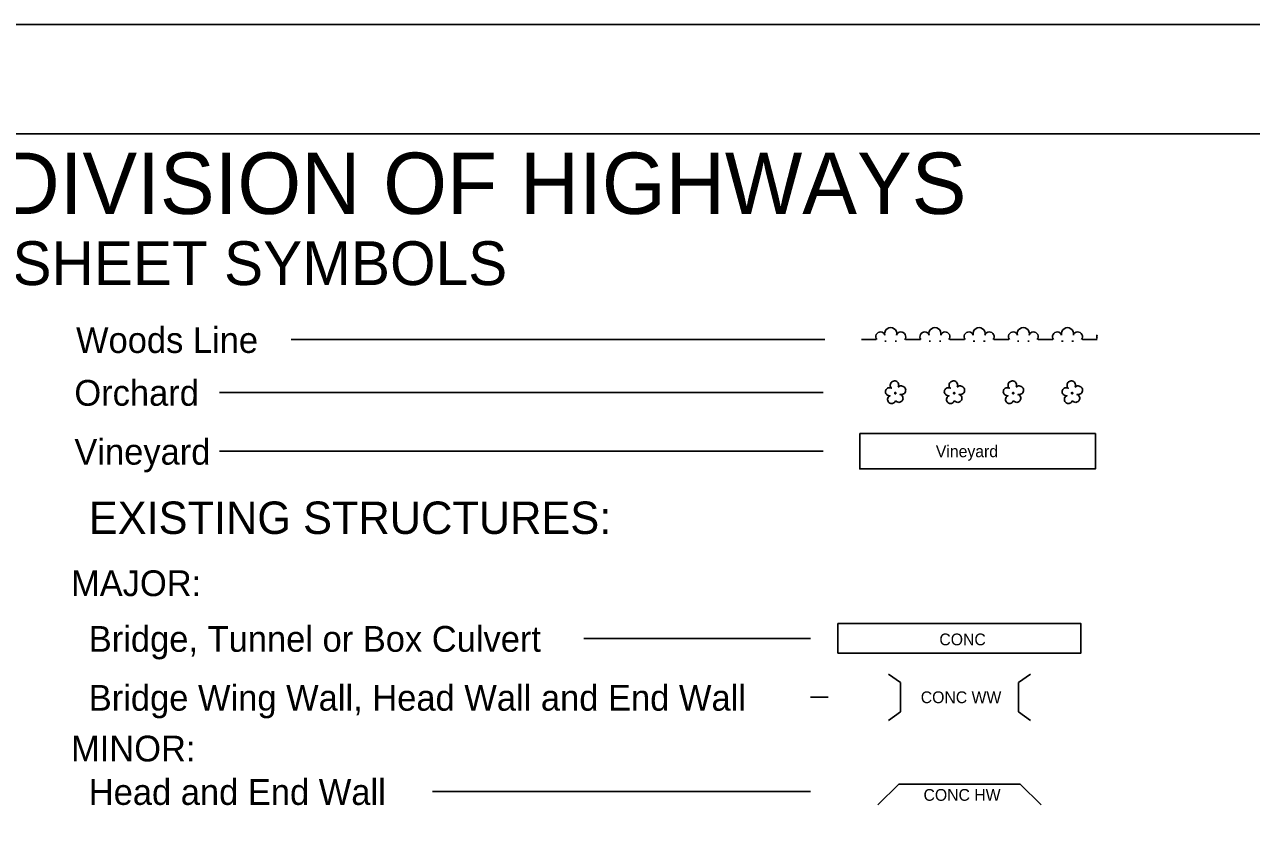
# Model space of a CAD drawing. Extents: x 1855058 to 1858918, y 1540202 to 1542502.
# Drawn here: x 1857984.5 to 1858404.6, y 1542229.1 to 1542501.8 of the extents above; entities that cross this region are included whole.
import ezdxf

# ---------------------------------------------------------------- set-up
doc = ezdxf.new("R2010")
doc.units = 0
for name, color, linetype in [('Default', 7, 'Continuous'), ('Exist Contamination Potential Cell', 7, 'Continuous'), ('Sheet Data Field CELL', 7, 'Continuous'), ('Sheet Symbology CELL', 7, 'Continuous')]:
    doc.layers.add(name, color=color, linetype=linetype)

msp = doc.modelspace()

# ---------------------------------------------------------------- linework, layer by layer
at = {"layer": 'Default'}
msp.add_lwpolyline([(1857118.6, 1542501.77), (1857118.6, 1541401.77), (1858818.6, 1541401.77), (1858818.6, 1542501.77)], close=True, dxfattribs=at)
at = {"layer": 'Exist Contamination Potential Cell'}
msp.add_line((1858818.6, 1542501.77), (1857118.6, 1542501.77), dxfattribs=at)
at = {"layer": 'Sheet Data Field CELL'}
for p, q in [((1858258.58, 1542393.83), (1858075.83, 1542393.83)), ((1858271.08, 1542393.83), (1858276.13, 1542393.83)), ((1858279.1, 1542393.33), (1858279.61, 1542393.33)), ((1858282.63, 1542393.33), (1858283.14, 1542393.33)), ((1858286.21, 1542393.83), (1858291.26, 1542393.83)), ((1858294.24, 1542393.33), (1858294.74, 1542393.33)), ((1858297.77, 1542393.33), (1858298.27, 1542393.33)), ((1858301.35, 1542393.83), (1858306.39, 1542393.83)), ((1858309.37, 1542393.33), (1858309.87, 1542393.33)), ((1858312.9, 1542393.33), (1858313.41, 1542393.33)), ((1858316.48, 1542393.83), (1858321.53, 1542393.83)), ((1858324.5, 1542393.33), (1858325.01, 1542393.33)), ((1858328.04, 1542393.33), (1858328.54, 1542393.33)), ((1858331.62, 1542393.83), (1858336.66, 1542393.83)), ((1858339.64, 1542393.33), (1858340.14, 1542393.33)), ((1858343.17, 1542393.33), (1858343.67, 1542393.33)), ((1858346.75, 1542393.83), (1858351.8, 1542393.83)), ((1858258.01, 1542375.74), (1858051.24, 1542375.74)), ((1858258.01, 1542355.56), (1858051.24, 1542355.56)), ((1858253.65, 1542291.49), (1858176, 1542291.49)), ((1858280.34, 1542279.24), (1858284.48, 1542276.36)), ((1858328.97, 1542279.24), (1858324.83, 1542276.36)), ((1858284.48, 1542276.36), (1858284.48, 1542266.27)), ((1858324.83, 1542276.36), (1858324.83, 1542266.27)), ((1858253.65, 1542271.31), (1858259.69, 1542271.31)), ((1858280.34, 1542263.38), (1858284.48, 1542266.27)), ((1858328.97, 1542263.38), (1858324.83, 1542266.27)), ((1858276.71, 1542234.42), (1858283.85, 1542241.55)), ((1858283.85, 1542241.55), (1858325.46, 1542241.55)), ((1858325.46, 1542241.55), (1858332.6, 1542234.42)), ((1858253.65, 1542239.03), (1858124.21, 1542239.03))]:
    msp.add_line(p, q, dxfattribs=at)
for points in [[(1858283.68, 1542377.51), (1858283.83, 1542377.81), (1858283.88, 1542378.11), (1858283.83, 1542378.42), (1858283.78, 1542378.72), (1858283.63, 1542378.97), (1858283.48, 1542379.22), (1858283.22, 1542379.43), (1858282.97, 1542379.58), (1858282.62, 1542379.68), (1858282.37, 1542379.68), (1858282.06, 1542379.63), (1858281.76, 1542379.53), (1858281.51, 1542379.38), (1858281.26, 1542379.17), (1858281.1, 1542378.87), (1858281, 1542378.62), (1858280.95, 1542378.32), (1858280.95, 1542378.01), (1858281, 1542377.71), (1858281.15, 1542377.46), (1858281.36, 1542377.16), (1858281.1, 1542377.31), (1858280.8, 1542377.36), (1858280.5, 1542377.36), (1858280.25, 1542377.26), (1858279.99, 1542377.16), (1858279.74, 1542376.95), (1858279.54, 1542376.75), (1858279.39, 1542376.5), (1858279.34, 1542376.25), (1858279.29, 1542375.89), (1858279.34, 1542375.64), (1858279.44, 1542375.39), (1858279.64, 1542375.14), (1858279.79, 1542374.94), (1858280.04, 1542374.78), (1858280.35, 1542374.63), (1858280.6, 1542374.58), (1858280.9, 1542374.58), (1858280.65, 1542374.48), (1858280.4, 1542374.28), (1858280.25, 1542374.08), (1858280.15, 1542373.78), (1858280.04, 1542373.47), (1858280.04, 1542373.22), (1858280.1, 1542372.92), (1858280.25, 1542372.67), (1858280.4, 1542372.41), (1858280.6, 1542372.21), (1858280.85, 1542372.06), (1858281.1, 1542371.96), (1858281.41, 1542371.96), (1858281.71, 1542371.96), (1858281.96, 1542372.01), (1858282.21, 1542372.21), (1858282.47, 1542372.36), (1858282.72, 1542372.82)], [(1858303.86, 1542377.51), (1858304.01, 1542377.81), (1858304.06, 1542378.11), (1858304.01, 1542378.42), (1858303.96, 1542378.72), (1858303.81, 1542378.97), (1858303.65, 1542379.22), (1858303.4, 1542379.43), (1858303.15, 1542379.58), (1858302.8, 1542379.68), (1858302.54, 1542379.68), (1858302.24, 1542379.63), (1858301.94, 1542379.53), (1858301.69, 1542379.38), (1858301.43, 1542379.17), (1858301.28, 1542378.87), (1858301.18, 1542378.62), (1858301.13, 1542378.32), (1858301.13, 1542378.01), (1858301.18, 1542377.71), (1858301.33, 1542377.46), (1858301.54, 1542377.16), (1858301.28, 1542377.31), (1858300.98, 1542377.36), (1858300.68, 1542377.36), (1858300.43, 1542377.26), (1858300.17, 1542377.16), (1858299.92, 1542376.95), (1858299.72, 1542376.75), (1858299.57, 1542376.5), (1858299.52, 1542376.25), (1858299.47, 1542375.89), (1858299.52, 1542375.64), (1858299.62, 1542375.39), (1858299.82, 1542375.14), (1858299.97, 1542374.94), (1858300.22, 1542374.78), (1858300.53, 1542374.63), (1858300.78, 1542374.58), (1858301.08, 1542374.58), (1858300.83, 1542374.48), (1858300.58, 1542374.28), (1858300.43, 1542374.08), (1858300.32, 1542373.78), (1858300.22, 1542373.47), (1858300.22, 1542373.22), (1858300.27, 1542372.92), (1858300.43, 1542372.67), (1858300.58, 1542372.41), (1858300.78, 1542372.21), (1858301.03, 1542372.06), (1858301.28, 1542371.96), (1858301.59, 1542371.96), (1858301.89, 1542371.96), (1858302.14, 1542372.01), (1858302.39, 1542372.21), (1858302.65, 1542372.36), (1858302.9, 1542372.82)], [(1858324.03, 1542377.51), (1858324.19, 1542377.81), (1858324.24, 1542378.11), (1858324.19, 1542378.42), (1858324.14, 1542378.72), (1858323.98, 1542378.97), (1858323.83, 1542379.22), (1858323.58, 1542379.43), (1858323.33, 1542379.58), (1858322.98, 1542379.68), (1858322.72, 1542379.68), (1858322.42, 1542379.63), (1858322.12, 1542379.53), (1858321.87, 1542379.38), (1858321.61, 1542379.17), (1858321.46, 1542378.87), (1858321.36, 1542378.62), (1858321.31, 1542378.32), (1858321.31, 1542378.01), (1858321.36, 1542377.71), (1858321.51, 1542377.46), (1858321.71, 1542377.16), (1858321.46, 1542377.31), (1858321.16, 1542377.36), (1858320.86, 1542377.36), (1858320.6, 1542377.26), (1858320.35, 1542377.16), (1858320.1, 1542376.95), (1858319.9, 1542376.75), (1858319.75, 1542376.5), (1858319.7, 1542376.25), (1858319.65, 1542375.89), (1858319.7, 1542375.64), (1858319.8, 1542375.39), (1858320, 1542375.14), (1858320.15, 1542374.94), (1858320.4, 1542374.78), (1858320.71, 1542374.63), (1858320.96, 1542374.58), (1858321.26, 1542374.58), (1858321.01, 1542374.48), (1858320.76, 1542374.28), (1858320.6, 1542374.08), (1858320.5, 1542373.78), (1858320.4, 1542373.47), (1858320.4, 1542373.22), (1858320.45, 1542372.92), (1858320.6, 1542372.67), (1858320.76, 1542372.41), (1858320.96, 1542372.21), (1858321.21, 1542372.06), (1858321.46, 1542371.96), (1858321.76, 1542371.96), (1858322.07, 1542371.96), (1858322.32, 1542372.01), (1858322.57, 1542372.21), (1858322.82, 1542372.36), (1858323.08, 1542372.82)], [(1858344.21, 1542377.51), (1858344.36, 1542377.81), (1858344.42, 1542378.11), (1858344.36, 1542378.42), (1858344.31, 1542378.72), (1858344.16, 1542378.97), (1858344.01, 1542379.22), (1858343.76, 1542379.43), (1858343.51, 1542379.58), (1858343.15, 1542379.68), (1858342.9, 1542379.68), (1858342.6, 1542379.63), (1858342.3, 1542379.53), (1858342.04, 1542379.38), (1858341.79, 1542379.17), (1858341.64, 1542378.87), (1858341.54, 1542378.62), (1858341.49, 1542378.32), (1858341.49, 1542378.01), (1858341.54, 1542377.71), (1858341.69, 1542377.46), (1858341.89, 1542377.16), (1858341.64, 1542377.31), (1858341.34, 1542377.36), (1858341.04, 1542377.36), (1858340.78, 1542377.26), (1858340.53, 1542377.16), (1858340.28, 1542376.95), (1858340.08, 1542376.75), (1858339.93, 1542376.5), (1858339.88, 1542376.25), (1858339.82, 1542375.89), (1858339.88, 1542375.64), (1858339.98, 1542375.39), (1858340.18, 1542375.14), (1858340.33, 1542374.94), (1858340.58, 1542374.78), (1858340.88, 1542374.63), (1858341.14, 1542374.58), (1858341.44, 1542374.58), (1858341.19, 1542374.48), (1858340.93, 1542374.28), (1858340.78, 1542374.08), (1858340.68, 1542373.78), (1858340.58, 1542373.47), (1858340.58, 1542373.22), (1858340.63, 1542372.92), (1858340.78, 1542372.67), (1858340.93, 1542372.41), (1858341.14, 1542372.21), (1858341.39, 1542372.06), (1858341.64, 1542371.96), (1858341.94, 1542371.96), (1858342.25, 1542371.96), (1858342.5, 1542372.01), (1858342.75, 1542372.21), (1858343, 1542372.36), (1858343.25, 1542372.82)], [(1858282.82, 1542375.74), (1858282.67, 1542375.74), (1858282.57, 1542375.69), (1858282.47, 1542375.64), (1858282.47, 1542375.49), (1858282.47, 1542375.39), (1858282.57, 1542375.29), (1858282.72, 1542375.29), (1858282.82, 1542375.29), (1858282.92, 1542375.39), (1858282.97, 1542375.54), (1858282.92, 1542375.64), (1858282.82, 1542375.74)], [(1858282.72, 1542372.82), (1858283.32, 1542372.46), (1858283.63, 1542372.36), (1858283.93, 1542372.31), (1858284.23, 1542372.36), (1858284.48, 1542372.46), (1858284.74, 1542372.62), (1858284.99, 1542372.82), (1858285.14, 1542373.07), (1858285.24, 1542373.32), (1858285.34, 1542373.62), (1858285.29, 1542373.93), (1858285.24, 1542374.23), (1858285.04, 1542374.53), (1858284.89, 1542374.73), (1858284.64, 1542374.89), (1858284.33, 1542375.04), (1858284.64, 1542374.99), (1858284.99, 1542374.99), (1858285.24, 1542375.09), (1858285.54, 1542375.24), (1858285.8, 1542375.39), (1858286, 1542375.64), (1858286.15, 1542375.94), (1858286.2, 1542376.25), (1858286.25, 1542376.55), (1858286.2, 1542376.85), (1858286.1, 1542377.16), (1858285.9, 1542377.41), (1858285.64, 1542377.66), (1858285.39, 1542377.81), (1858285.09, 1542377.91), (1858284.79, 1542377.96), (1858284.48, 1542377.96), (1858284.18, 1542377.86), (1858283.93, 1542377.71), (1858283.68, 1542377.51)], [(1858303, 1542375.74), (1858302.85, 1542375.74), (1858302.75, 1542375.69), (1858302.65, 1542375.64), (1858302.65, 1542375.49), (1858302.65, 1542375.39), (1858302.75, 1542375.29), (1858302.9, 1542375.29), (1858303, 1542375.29), (1858303.1, 1542375.39), (1858303.15, 1542375.54), (1858303.1, 1542375.64), (1858303, 1542375.74)], [(1858302.9, 1542372.82), (1858303.5, 1542372.46), (1858303.81, 1542372.36), (1858304.11, 1542372.31), (1858304.41, 1542372.36), (1858304.66, 1542372.46), (1858304.92, 1542372.62), (1858305.17, 1542372.82), (1858305.32, 1542373.07), (1858305.42, 1542373.32), (1858305.52, 1542373.62), (1858305.47, 1542373.93), (1858305.42, 1542374.23), (1858305.22, 1542374.53), (1858305.07, 1542374.73), (1858304.81, 1542374.89), (1858304.51, 1542375.04), (1858304.81, 1542374.99), (1858305.17, 1542374.99), (1858305.42, 1542375.09), (1858305.72, 1542375.24), (1858305.97, 1542375.39), (1858306.18, 1542375.64), (1858306.33, 1542375.94), (1858306.38, 1542376.25), (1858306.43, 1542376.55), (1858306.38, 1542376.85), (1858306.28, 1542377.16), (1858306.08, 1542377.41), (1858305.82, 1542377.66), (1858305.57, 1542377.81), (1858305.27, 1542377.91), (1858304.97, 1542377.96), (1858304.66, 1542377.96), (1858304.36, 1542377.86), (1858304.11, 1542377.71), (1858303.86, 1542377.51)], [(1858323.18, 1542375.74), (1858323.03, 1542375.74), (1858322.92, 1542375.69), (1858322.82, 1542375.64), (1858322.82, 1542375.49), (1858322.82, 1542375.39), (1858322.92, 1542375.29), (1858323.08, 1542375.29), (1858323.18, 1542375.29), (1858323.28, 1542375.39), (1858323.33, 1542375.54), (1858323.28, 1542375.64), (1858323.18, 1542375.74)], [(1858323.08, 1542372.82), (1858323.68, 1542372.46), (1858323.98, 1542372.36), (1858324.29, 1542372.31), (1858324.59, 1542372.36), (1858324.84, 1542372.46), (1858325.09, 1542372.62), (1858325.35, 1542372.82), (1858325.5, 1542373.07), (1858325.6, 1542373.32), (1858325.7, 1542373.62), (1858325.65, 1542373.93), (1858325.6, 1542374.23), (1858325.4, 1542374.53), (1858325.25, 1542374.73), (1858324.99, 1542374.89), (1858324.69, 1542375.04), (1858324.99, 1542374.99), (1858325.35, 1542374.99), (1858325.6, 1542375.09), (1858325.9, 1542375.24), (1858326.15, 1542375.39), (1858326.36, 1542375.64), (1858326.51, 1542375.94), (1858326.56, 1542376.25), (1858326.61, 1542376.55), (1858326.56, 1542376.85), (1858326.46, 1542377.16), (1858326.25, 1542377.41), (1858326, 1542377.66), (1858325.75, 1542377.81), (1858325.45, 1542377.91), (1858325.14, 1542377.96), (1858324.84, 1542377.96), (1858324.54, 1542377.86), (1858324.29, 1542377.71), (1858324.03, 1542377.51)], [(1858343.36, 1542375.74), (1858343.2, 1542375.74), (1858343.1, 1542375.69), (1858343, 1542375.64), (1858343, 1542375.49), (1858343, 1542375.39), (1858343.1, 1542375.29), (1858343.25, 1542375.29), (1858343.36, 1542375.29), (1858343.46, 1542375.39), (1858343.51, 1542375.54), (1858343.46, 1542375.64), (1858343.36, 1542375.74)], [(1858343.25, 1542372.82), (1858343.86, 1542372.46), (1858344.16, 1542372.36), (1858344.47, 1542372.31), (1858344.77, 1542372.36), (1858345.02, 1542372.46), (1858345.27, 1542372.62), (1858345.53, 1542372.82), (1858345.68, 1542373.07), (1858345.78, 1542373.32), (1858345.88, 1542373.62), (1858345.83, 1542373.93), (1858345.78, 1542374.23), (1858345.58, 1542374.53), (1858345.42, 1542374.73), (1858345.17, 1542374.89), (1858344.87, 1542375.04), (1858345.17, 1542374.99), (1858345.53, 1542374.99), (1858345.78, 1542375.09), (1858346.08, 1542375.24), (1858346.33, 1542375.39), (1858346.53, 1542375.64), (1858346.69, 1542375.94), (1858346.74, 1542376.25), (1858346.79, 1542376.55), (1858346.74, 1542376.85), (1858346.63, 1542377.16), (1858346.43, 1542377.41), (1858346.18, 1542377.66), (1858345.93, 1542377.81), (1858345.63, 1542377.91), (1858345.32, 1542377.96), (1858345.02, 1542377.96), (1858344.72, 1542377.86), (1858344.47, 1542377.71), (1858344.21, 1542377.51)], [(1858270.51, 1542361.62), (1858351.23, 1542361.62), (1858351.23, 1542349.51), (1858270.51, 1542349.51), (1858270.51, 1542361.62)], [(1858263.04, 1542296.54), (1858346.27, 1542296.54), (1858346.27, 1542286.45), (1858263.04, 1542286.45), (1858263.04, 1542296.54)]]:
    msp.add_lwpolyline(points, dxfattribs=at)
for centre, radius, start, end in [((1858277.59, 1542394.85), 1.6, 18.435, 219.2315), ((1858281.12, 1542395.86), 2.08, 345.9638, 194.0362), ((1858284.65, 1542394.85), 1.6, 320.7685, 161.5651), ((1858292.72, 1542394.85), 1.6, 18.435, 219.2315), ((1858296.25, 1542395.86), 2.08, 345.9638, 194.0362), ((1858299.78, 1542394.85), 1.6, 320.7685, 161.5651), ((1858307.85, 1542394.85), 1.6, 18.435, 219.2315), ((1858311.39, 1542395.86), 2.08, 345.9638, 194.0362), ((1858314.92, 1542394.85), 1.6, 320.7685, 161.5651), ((1858322.99, 1542394.85), 1.6, 18.435, 219.2315), ((1858326.52, 1542395.86), 2.08, 345.9638, 194.0362), ((1858330.05, 1542394.85), 1.6, 320.7685, 161.5651), ((1858338.12, 1542394.85), 1.6, 18.435, 219.2315), ((1858341.65, 1542395.86), 2.08, 345.9638, 194.0362), ((1858345.18, 1542394.85), 1.6, 320.7685, 161.5651), ((1858353.26, 1542394.85), 1.6, 156.251, 203.749)]:
    msp.add_arc(centre, radius, start, end, dxfattribs=at)
at = {"layer": 'Sheet Symbology CELL'}
msp.add_line((1858781.1, 1542464.27), (1857156.1, 1542464.27), dxfattribs=at)

# ---------------------------------------------------------------- texts
at = {"layer": 'Sheet Data Field CELL'}
for s, height, p in [('STATE OF NORTH CAROLINA, DIVISION OF HIGHWAYS', 21, (1857564.35, 1542436.88)), ('CONVENTIONAL  PLAN SHEET SYMBOLS', 15, (1857752.99, 1542412.51)), ('Woods Line', 8.828, (1858002.14, 1542389.26)), ('Orchard', 8.828, (1858001.57, 1542371.18)), ('Vineyard', 8.828, (1858001.57, 1542351)), ('EXISTING STRUCTURES:', 11.0983, (1858006.5, 1542327.26)), ('MAJOR:', 8.828, (1858000.42, 1542305.96)), ('Bridge, Tunnel or Box Culvert', 8.8282, (1858006.5, 1542286.9)), ('CONC', 4.036, (1858297.78, 1542289.11)), ('Bridge Wing Wall, Head Wall and End Wall', 8.8282, (1858006.5, 1542266.72)), ('MINOR:', 8.828, (1858000.42, 1542249.33)), ('Head and End Wall', 8.8282, (1858006.5, 1542234.44)), ('CONC HW', 4.036, (1858292.35, 1542235.84))]:
    msp.add_text(s, height=height, dxfattribs=at).set_placement(p)
for s, p in [('Vineyard', (1858296.57, 1542353.55)), ('CONC WW', (1858291.41, 1542269.29))]:
    msp.add_text(s, height=4.036, rotation=0, dxfattribs=at).set_placement(p)

doc.saveas('drawing.dxf')
